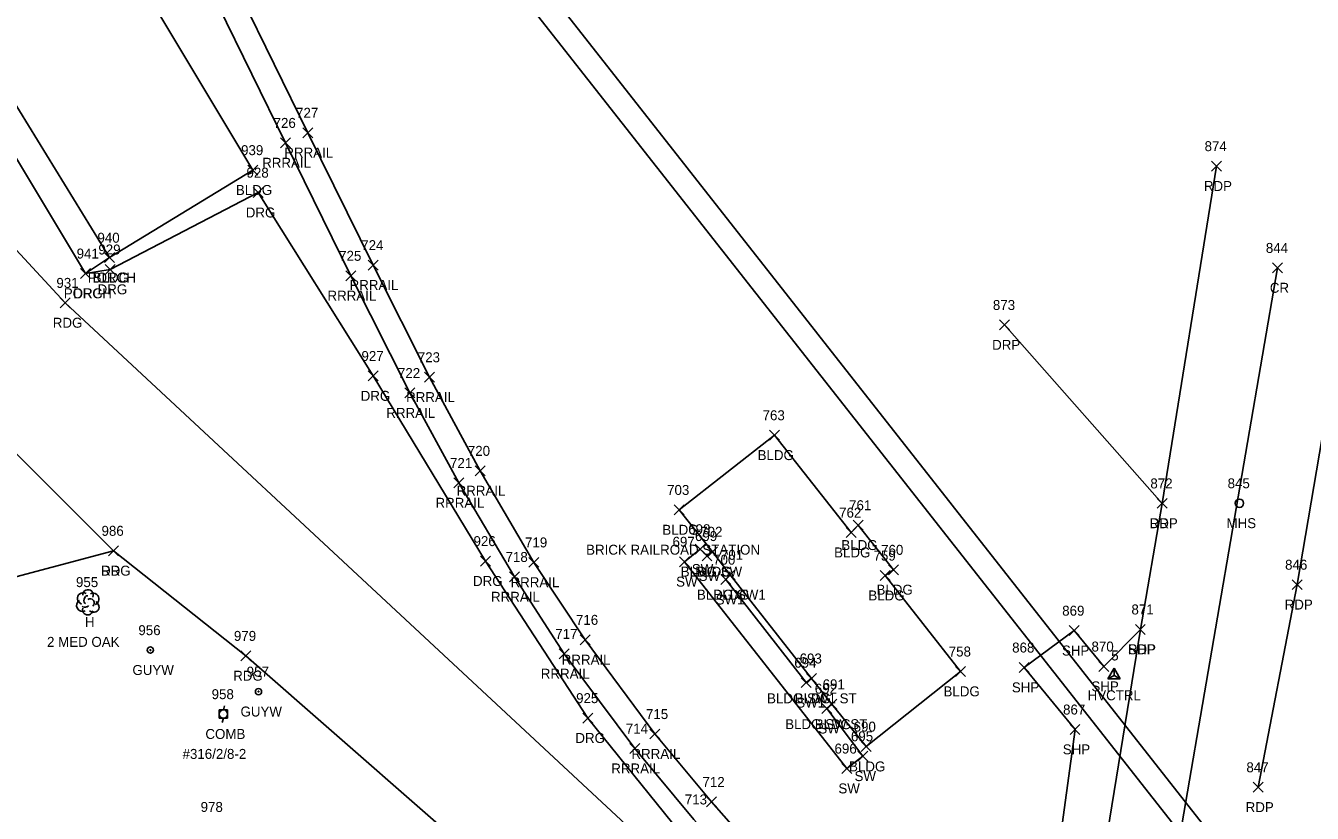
# Model space of a CAD drawing. Extents: x 1615599 to 1619911, y 273782 to 280437.
# Drawn here: x 1616311.5 to 1616569.8, y 279843.1 to 280001.3 of the extents above; entities that cross this region are included whole.
import ezdxf

# ---------------------------------------------------------------- set-up
doc = ezdxf.new("R2010")
doc.units = 0
for name, color, linetype in [('C_A', 7, 'Continuous'), ('C_I', 7, 'Continuous'), ('CPSM', 7, 'Continuous'), ('L_A', 7, 'Continuous'), ('L_C', 7, 'Continuous'), ('L_I', 7, 'Continuous'), ('L_TIC', 7, 'Continuous'), ('LBC', 7, 'Continuous'), ('LBF', 7, 'Continuous'), ('LTD', 7, 'Continuous'), ('P_A', 7, 'Continuous'), ('P_I', 7, 'Continuous'), ('P_TIC', 7, 'Continuous'), ('PET', 7, 'Continuous'), ('PEU', 7, 'Continuous'), ('PRC', 7, 'Continuous'), ('PSP', 7, 'Continuous'), ('R_A', 7, 'Continuous'), ('R_I', 7, 'Continuous'), ('R_TIC', 7, 'Continuous'), ('RDG', 7, 'Continuous'), ('RDP', 7, 'Continuous'), ('RR', 7, 'Continuous'), ('RSW', 7, 'Continuous'), ('U_A', 7, 'Continuous'), ('U_C', 7, 'Continuous'), ('U_I', 7, 'Continuous'), ('UP', 7, 'Continuous'), ('UPGW', 7, 'Continuous'), ('USMH', 7, 'Continuous')]:
    doc.layers.add(name, color=color, linetype=linetype)

msp = doc.modelspace()

# ---------------------------------------------------------------- linework, layer by layer
at = {"layer": 'CPSM'}
for p, q in [((1616528.77, 279870.08), (1616530.02, 279872.24)), ((1616531.27, 279870.08), (1616530.02, 279872.24)), ((1616530.03, 279870.8), (1616530.02, 279872.24)), ((1616528.77, 279870.08), (1616530.03, 279870.8)), ((1616528.77, 279870.08), (1616531.27, 279870.08)), ((1616530.03, 279870.8), (1616530.03, 279870.8)), ((1616530.03, 279870.8), (1616531.27, 279870.08))]:
    msp.add_line(p, q, dxfattribs=at)
at = {"layer": 'L_TIC'}
for points in [[(1616356.12, 279971.28), (1616358.12, 279973.28)], [(1616358.12, 279971.28), (1616356.12, 279973.28)], [(1616327.36, 279953.69), (1616329.36, 279955.69)], [(1616329.36, 279953.69), (1616327.36, 279955.69)], [(1616327.36, 279953.69), (1616329.36, 279955.69)], [(1616329.36, 279953.69), (1616327.36, 279955.69)], [(1616322.53, 279950.52), (1616324.53, 279952.52)], [(1616324.53, 279950.52), (1616322.53, 279952.52)], [(1616460.87, 279918.04), (1616462.87, 279920.04)], [(1616462.87, 279918.04), (1616460.87, 279920.04)], [(1616460.87, 279918.04), (1616462.87, 279920.04)], [(1616462.87, 279918.04), (1616460.87, 279920.04)], [(1616441.73, 279903.04), (1616443.73, 279905.04)], [(1616443.73, 279903.04), (1616441.73, 279905.04)], [(1616476.24, 279898.49), (1616478.24, 279900.49)], [(1616478.24, 279898.49), (1616476.24, 279900.49)], [(1616477.68, 279899.97), (1616479.68, 279901.97)], [(1616479.68, 279899.97), (1616477.68, 279901.97)], [(1616448.38, 279894.64), (1616450.38, 279896.64)], [(1616450.38, 279894.64), (1616448.38, 279896.64)], [(1616451.97, 279890.01), (1616453.97, 279892.01)], [(1616453.97, 279890.01), (1616451.97, 279892.01)], [(1616483.1, 279889.85), (1616485.1, 279891.85)], [(1616485.1, 279889.85), (1616483.1, 279891.85)], [(1616484.75, 279891.01), (1616486.75, 279893.01)], [(1616486.75, 279891.01), (1616484.75, 279893.01)], [(1616468.31, 279869.19), (1616470.31, 279871.19)], [(1616470.31, 279869.19), (1616468.31, 279871.19)], [(1616498.2, 279870.59), (1616500.2, 279872.59)], [(1616500.2, 279870.59), (1616498.2, 279872.59)], [(1616472.36, 279864), (1616474.36, 279866)], [(1616474.36, 279864), (1616472.36, 279866)], [(1616479.23, 279855.51), (1616481.23, 279857.51)], [(1616481.23, 279855.51), (1616479.23, 279857.51)], [(1616479.23, 279855.51), (1616481.23, 279857.51)], [(1616481.23, 279855.51), (1616479.23, 279857.51)]]:
    msp.add_lwpolyline(points, dxfattribs=at)
at = {"layer": 'LBC'}
for points in [[(1616260.86, 280142.43), (1616270.81, 280125.23), (1616271.71, 280125.76), (1616321.31, 280044.41), (1616318.76, 280042.81), (1616339.97, 280008.45), (1616336.65, 280006.38), (1616357.12, 279972.28), (1616328.36, 279954.69), (1616257.78, 280069.65), (1616226.23, 280122.19)], [(1616480.23, 279856.51), (1616473.36, 279865), (1616469.31, 279870.19), (1616452.97, 279891.01), (1616449.38, 279895.64), (1616442.73, 279904.04), (1616461.87, 279919.04)], [(1616480.23, 279856.51), (1616499.2, 279871.59), (1616484.1, 279890.85), (1616485.75, 279892.01), (1616478.68, 279900.97), (1616477.24, 279899.49), (1616461.87, 279919.04)]]:
    msp.add_lwpolyline(points, dxfattribs=at)
at = {"layer": 'LBF'}
msp.add_lwpolyline([(1616328.36, 279954.69), (1616323.53, 279951.52), (1616279.95, 280024.05), (1616274.42, 280020.51), (1616248.28, 280063.02), (1616257.78, 280069.65)], dxfattribs=at)
at = {"layer": 'LTD'}
msp.add_line((1616323.96, 279885.53), (1616323.96, 279885.53), dxfattribs=at)
msp.add_line((1616323.96, 279885.53), (1616323.96, 279885.53), dxfattribs=at)
msp.add_arc((1616324.01, 279886.96), 1.05, 335.5272, 180.9563, dxfattribs=at)
for centre, major_axis, ratio, start_param, end_param in [((1616323.17, 279886.19), (1.21, -0.51), 0.895232, 1.570796, 4.712389), ((1616323.75, 279885.98), (-0.208, -0.792), 0.645439, 3.141593, 6.283185), ((1616325, 279886.11), (-1.14, -0.48), 0.949671, 1.570796, 4.712389), ((1616322.88, 279884.82), (0.58, -1.04), 0.959034, 3.141593, 6.283185), ((1616323.96, 279884.03), (0.26, 1.06), 0.942809, 1.570796, 4.712389), ((1616323.5, 279884.78), (-0.625, -0.083), 0.423636, 0, 3.141593), ((1616324.46, 279885.36), (-0.5, 0.667), 0.989748, 3.141593, 6.283185), ((1616324.96, 279884.69), (-1.09, 0.79), 0.841452, 1.570796, 4.712389)]:
    msp.add_ellipse(centre, major_axis=major_axis, ratio=ratio, start_param=start_param, end_param=end_param, dxfattribs=at)
at = {"layer": 'P_TIC'}
for points in [[(1616549.57, 279972.08), (1616551.57, 279974.08)], [(1616551.57, 279972.08), (1616549.57, 279974.08)], [(1616561.87, 279951.64), (1616563.87, 279953.64)], [(1616563.87, 279951.64), (1616561.87, 279953.64)], [(1616318.46, 279944.62), (1616320.46, 279946.62)], [(1616320.46, 279944.62), (1616318.46, 279946.62)], [(1616538.68, 279904.35), (1616540.68, 279906.35)], [(1616540.68, 279904.35), (1616538.68, 279906.35)], [(1616328.14, 279894.83), (1616330.14, 279896.83)], [(1616330.14, 279894.83), (1616328.14, 279896.83)], [(1616565.79, 279888.02), (1616567.79, 279890.02)], [(1616567.79, 279888.02), (1616565.79, 279890.02)], [(1616521.04, 279878.79), (1616523.04, 279880.79)], [(1616523.04, 279878.79), (1616521.04, 279880.79)], [(1616534.31, 279879.04), (1616536.31, 279881.04)], [(1616536.31, 279879.04), (1616534.31, 279881.04)], [(1616534.31, 279879.04), (1616536.31, 279881.04)], [(1616536.31, 279879.04), (1616534.31, 279881.04)], [(1616354.68, 279873.73), (1616356.68, 279875.73)], [(1616356.68, 279873.73), (1616354.68, 279875.73)], [(1616510.98, 279871.39), (1616512.98, 279873.39)], [(1616512.98, 279871.39), (1616510.98, 279873.39)], [(1616526.95, 279871.59), (1616528.95, 279873.59)], [(1616528.95, 279871.59), (1616526.95, 279873.59)], [(1616521.19, 279858.94), (1616523.19, 279860.94)], [(1616523.19, 279858.94), (1616521.19, 279860.94)], [(1616557.96, 279847.34), (1616559.96, 279849.34)], [(1616559.96, 279847.34), (1616557.96, 279849.34)]]:
    msp.add_lwpolyline(points, dxfattribs=at)
at = {"layer": 'PET'}
for points in [[(1616501.73, 279478.79), (1616504.15, 279516.53), (1616502.36, 279521.09), (1616509.74, 279623.18), (1616513.26, 279680.58), (1616517.86, 279738.11), (1616521.66, 279796.02), (1616535.31, 279880.04), (1616539.68, 279905.35), (1616550.57, 279973.08)], [(1616577.39, 279951.25), (1616566.79, 279889.02), (1616558.96, 279848.34)]]:
    msp.add_lwpolyline(points, dxfattribs=at)
at = {"layer": 'PEU'}
for points in [[(1616499.74, 279780.98), (1616479.11, 279797), (1616319.46, 279945.62), (1616274.32, 279994.35), (1616255.18, 280018.22), (1616235.11, 280063.13), (1616219.63, 280113.45), (1616199.45, 280157.82), (1616176.87, 280194.27), (1616140.8, 280248.09)], [(1616486.88, 279757.56), (1616476.4, 279764.58), (1616449.89, 279788.09), (1616430.61, 279808), (1616410.01, 279827.22), (1616355.68, 279874.73), (1616329.14, 279895.83), (1616251.77, 279973.13), (1616240.04, 279993.6), (1616211.88, 280076.79), (1616204.14, 280097.8), (1616191.71, 280134.04), (1616179.76, 280157.24), (1616153.69, 280197.29), (1616148.4, 280204.31)]]:
    msp.add_lwpolyline(points, dxfattribs=at)
at = {"layer": 'PRC'}
msp.add_lwpolyline([(1616513.97, 279478.68), (1616523.34, 279622.43), (1616526.18, 279679.14), (1616531, 279739.46), (1616538.76, 279812.35), (1616562.87, 279952.64)], dxfattribs=at)
at = {"layer": 'PSP'}
msp.add_lwpolyline([(1616512.64, 279790.01), (1616522.19, 279859.94), (1616511.98, 279872.39), (1616522.04, 279879.79), (1616527.95, 279872.59), (1616535.31, 279880.04)], dxfattribs=at)
at = {"layer": 'R_TIC'}
for points in [[(1616367.15, 279978.78), (1616369.15, 279980.78)], [(1616369.15, 279978.78), (1616367.15, 279980.78)], [(1616362.7, 279976.75), (1616364.7, 279978.75)], [(1616364.7, 279976.75), (1616362.7, 279978.75)], [(1616357.21, 279966.76), (1616359.21, 279968.76)], [(1616359.21, 279966.76), (1616357.21, 279968.76)], [(1616380.25, 279952.2), (1616382.25, 279954.2)], [(1616382.25, 279952.2), (1616380.25, 279954.2)], [(1616322.53, 279950.52), (1616324.53, 279952.52)], [(1616324.53, 279950.52), (1616322.53, 279952.52)], [(1616327.46, 279951.33), (1616329.46, 279953.33)], [(1616329.46, 279951.33), (1616327.46, 279953.33)], [(1616375.81, 279950.06), (1616377.81, 279952.06)], [(1616377.81, 279950.06), (1616375.81, 279952.06)], [(1616507.06, 279940.18), (1616509.06, 279942.18)], [(1616509.06, 279940.18), (1616507.06, 279942.18)], [(1616380.28, 279929.94), (1616382.28, 279931.94)], [(1616382.28, 279929.94), (1616380.28, 279931.94)], [(1616391.59, 279929.69), (1616393.59, 279931.69)], [(1616393.59, 279929.69), (1616391.59, 279931.69)], [(1616387.61, 279926.52), (1616389.61, 279928.52)], [(1616389.61, 279926.52), (1616387.61, 279928.52)], [(1616401.73, 279910.89), (1616403.73, 279912.89)], [(1616403.73, 279910.89), (1616401.73, 279912.89)], [(1616397.5, 279908.46), (1616399.5, 279910.46)], [(1616399.5, 279908.46), (1616397.5, 279910.46)], [(1616538.68, 279904.35), (1616540.68, 279906.35)], [(1616540.68, 279904.35), (1616538.68, 279906.35)], [(1616445.94, 279895.15), (1616447.94, 279897.15)], [(1616447.94, 279895.15), (1616445.94, 279897.15)], [(1616328.14, 279894.83), (1616330.14, 279896.83)], [(1616330.14, 279894.83), (1616328.14, 279896.83)], [(1616402.84, 279892.76), (1616404.84, 279894.76)], [(1616404.84, 279892.76), (1616402.84, 279894.76)], [(1616412.56, 279892.5), (1616414.56, 279894.5)], [(1616414.56, 279892.5), (1616412.56, 279894.5)], [(1616442.79, 279892.63), (1616444.79, 279894.63)], [(1616444.79, 279892.63), (1616442.79, 279894.63)], [(1616447.3, 279893.78), (1616449.3, 279895.78)], [(1616449.3, 279893.78), (1616447.3, 279895.78)], [(1616448.38, 279894.64), (1616450.38, 279896.64)], [(1616450.38, 279894.64), (1616448.38, 279896.64)], [(1616451.97, 279890.01), (1616453.97, 279892.01)], [(1616453.97, 279890.01), (1616451.97, 279892.01)], [(1616408.64, 279889.58), (1616410.64, 279891.58)], [(1616410.64, 279889.58), (1616408.64, 279891.58)], [(1616451.06, 279889.04), (1616453.06, 279891.04)], [(1616453.06, 279889.04), (1616451.06, 279891.04)], [(1616422.84, 279876.95), (1616424.84, 279878.95)], [(1616424.84, 279876.95), (1616422.84, 279878.95)], [(1616418.63, 279874.14), (1616420.63, 279876.14)], [(1616420.63, 279874.14), (1616418.63, 279876.14)], [(1616468.31, 279869.19), (1616470.31, 279871.19)], [(1616470.31, 279869.19), (1616468.31, 279871.19)], [(1616467.24, 279868.34), (1616469.24, 279870.34)], [(1616469.24, 279868.34), (1616467.24, 279870.34)], [(1616472.36, 279864), (1616474.36, 279866)], [(1616474.36, 279864), (1616472.36, 279866)], [(1616471.35, 279863.13), (1616473.35, 279865.13)], [(1616473.35, 279863.13), (1616471.35, 279865.13)], [(1616423.38, 279861.23), (1616425.38, 279863.23)], [(1616425.38, 279861.23), (1616423.38, 279863.23)], [(1616436.84, 279858.03), (1616438.84, 279860.03)], [(1616438.84, 279858.03), (1616436.84, 279860.03)], [(1616432.79, 279855.11), (1616434.79, 279857.11)], [(1616434.79, 279855.11), (1616432.79, 279857.11)], [(1616478.61, 279853.57), (1616480.61, 279855.57)], [(1616480.61, 279853.57), (1616478.61, 279855.57)], [(1616475.37, 279851.1), (1616477.37, 279853.1)], [(1616477.37, 279851.1), (1616475.37, 279853.1)], [(1616448.19, 279844.4), (1616450.19, 279846.4)], [(1616450.19, 279844.4), (1616448.19, 279846.4)]]:
    msp.add_lwpolyline(points, dxfattribs=at)
at = {"layer": 'RDG'}
for points in [[(1616479.11, 279797), (1616452.08, 279827.9), (1616424.38, 279862.23), (1616403.84, 279893.76), (1616381.28, 279930.94), (1616358.21, 279967.76), (1616328.46, 279952.33), (1616323.53, 279951.52)], [(1616329.14, 279895.83), (1616292.13, 279885.95), (1616252.07, 279884.53), (1616218.26, 279864.37), (1616210.2, 279851.21)]]:
    msp.add_lwpolyline(points, dxfattribs=at)
at = {"layer": 'RDP'}
msp.add_lwpolyline([(1616539.68, 279905.35), (1616508.06, 279941.18)], dxfattribs=at)
at = {"layer": 'RR'}
for points in [[(1618863.67, 276894.43), (1618803.13, 276971.25), (1618287.89, 277627.49), (1618272.16, 277647.46), (1617630.42, 278463.6), (1617620.37, 278476.22), (1617582.75, 278523.92), (1617266.97, 278926.89), (1616715.35, 279628.09), (1616637.52, 279726.94), (1616590.36, 279786.85), (1616151.06, 280346.19)], [(1618859.75, 276891.53), (1618799.24, 276968.15), (1618284.94, 277623.12), (1618268.81, 277643.64), (1617626.81, 278460.24), (1617616.13, 278473.64), (1617546.95, 278561.72), (1617499.49, 278621.79), (1617406.55, 278740.52), (1617357.63, 278802.9), (1617271.97, 278912.55), (1616838.51, 279463.88), (1616791.25, 279524.04), (1616711.4, 279625.23), (1616195.43, 280281.84), (1616147.06, 280342.91)], [(1616578.78, 279727.56), (1616559.36, 279743.25), (1616547.84, 279752.47), (1616532.45, 279765.05), (1616519.03, 279776.56), (1616509.64, 279784.79), (1616496.17, 279796.99), (1616483.02, 279809.54), (1616469.51, 279823.1), (1616459.09, 279834.19), (1616449.19, 279845.4), (1616437.84, 279859.03), (1616423.84, 279877.95), (1616413.56, 279893.5), (1616402.73, 279911.89), (1616392.59, 279930.69), (1616381.25, 279953.2), (1616368.15, 279979.78), (1616347.86, 280021.18)], [(1616575.93, 279723.48), (1616556.08, 279739.45), (1616545.23, 279748.16), (1616531.41, 279759.44), (1616516, 279772.44), (1616507.27, 279780.31), (1616493.17, 279793.09), (1616479.92, 279805.59), (1616465.51, 279820.07), (1616455.17, 279831.23), (1616445.64, 279841.88), (1616433.79, 279856.11), (1616419.63, 279875.14), (1616409.64, 279890.58), (1616398.5, 279909.46), (1616388.61, 279927.52), (1616376.81, 279951.06), (1616363.7, 279977.75), (1616343.37, 280019.21)]]:
    msp.add_lwpolyline(points, dxfattribs=at)
at = {"layer": 'RSW'}
for points in [[(1616473.36, 279865), (1616472.35, 279864.13), (1616479.61, 279854.57), (1616476.37, 279852.1), (1616443.79, 279893.63), (1616446.94, 279896.15), (1616448.3, 279894.78), (1616449.38, 279895.64)], [(1616469.31, 279870.19), (1616468.24, 279869.34), (1616452.06, 279890.04), (1616452.97, 279891.01)]]:
    msp.add_lwpolyline(points, dxfattribs=at)
at = {"layer": 'UP'}
for p, q in [((1616350.37, 279862.2), (1616350.37, 279863.86)), ((1616350.37, 279863.86), (1616352.03, 279863.86)), ((1616351.45, 279864.7), (1616351.2, 279863.86)), ((1616352.03, 279863.86), (1616352.03, 279862.2)), ((1616352.03, 279862.2), (1616350.37, 279862.2)), ((1616350.95, 279861.36), (1616351.2, 279862.2)), ((1616351.2, 279863.03), (1616351.2, 279863.03))]:
    msp.add_line(p, q, dxfattribs=at)
msp.add_circle((1616351.2, 279863.03), 0.833, dxfattribs=at)
at = {"layer": 'UPGW'}
for centre, radius in [((1616336.55, 279875.88), 0.625), ((1616336.55, 279875.88), 0.0833), ((1616358.25, 279867.54), 0.625), ((1616358.25, 279867.54), 0.0833)]:
    msp.add_circle(centre, radius, dxfattribs=at)
at = {"layer": 'USMH'}
for p, q in [((1616555.2, 279905.37), (1616555.2, 279905.37)), ((1616556.03, 279905.37), (1616556.03, 279905.37))]:
    msp.add_line(p, q, dxfattribs=at)
msp.add_circle((1616555.2, 279905.37), 0.833, dxfattribs=at)

# ---------------------------------------------------------------- texts
at = {"layer": 'C_A'}
msp.add_text('HVCTRL', height=2, dxfattribs=at).set_placement((1616524.72, 279865.8))
at = {"layer": 'C_I'}
msp.add_text('5', height=2, dxfattribs=at).set_placement((1616529.46, 279873.8))
at = {"layer": 'L_A'}
for s, p in [('BLDG', (1616353.71, 279967.28)), ('PORCH', (1616323.98, 279949.69)), ('BLDG', (1616324.95, 279949.69)), ('PORCH', (1616319.16, 279946.52)), ('BLDG', (1616458.46, 279914.04)), ('BLDG', (1616458.46, 279914.04)), ('BLDG', (1616439.33, 279899.04)), ('BLDG', (1616475.27, 279895.97)), ('BLDG', (1616473.83, 279894.49)), ('BLDG', (1616445.97, 279890.64)), ('BLDG', (1616449.56, 279886.01)), ('BLDG', (1616480.7, 279885.85)), ('BLDG', (1616482.34, 279887.01)), ('H', (1616323.39, 279880.53)), ('BLDG', (1616495.79, 279866.59)), ('BLDG', (1616465.9, 279865.19)), ('BLDG', (1616469.95, 279860)), ('BLDG', (1616476.82, 279851.51)), ('BLDG', (1616476.82, 279851.51))]:
    msp.add_text(s, height=2, dxfattribs=at).set_placement(p)
at = {"layer": 'L_C'}
for s, p in [('BRICK RAILROAD STATION', (1616424.03, 279895.04)), ('2 MED OAK', (1616315.79, 279876.53))]:
    msp.add_text(s, height=2, dxfattribs=at).set_placement(p)
at = {"layer": 'L_I'}
for s, p in [('939', (1616354.75, 279975.28)), ('940', (1616325.91, 279957.69)), ('940', (1616325.91, 279957.69)), ('941', (1616321.74, 279954.52)), ('763', (1616459.46, 279922.04)), ('763', (1616459.46, 279922.04)), ('703', (1616440.29, 279907.04)), ('761', (1616476.83, 279903.97)), ('762', (1616474.83, 279902.49)), ('702', (1616446.94, 279898.64)), ('760', (1616483.26, 279895.01)), ('701', (1616451.09, 279894.01)), ('759', (1616481.73, 279893.85)), ('955', (1616321.6, 279888.53)), ('758', (1616496.84, 279874.59)), ('693', (1616466.9, 279873.19)), ('691', (1616471.52, 279868)), ('690', (1616477.74, 279859.51)), ('690', (1616477.74, 279859.51))]:
    msp.add_text(s, height=2, dxfattribs=at).set_placement(p)
at = {"layer": 'P_A'}
for s, p in [('RDP', (1616548.06, 279968.08)), ('CR', (1616561.31, 279947.64)), ('RDG', (1616316.95, 279940.62)), ('RDP', (1616537.17, 279900.35)), ('RDG', (1616326.63, 279890.83)), ('RDP', (1616564.28, 279884.02)), ('SHP', (1616519.57, 279874.79)), ('SHP', (1616532.85, 279875.04)), ('RDP', (1616532.8, 279875.04)), ('RDG', (1616353.17, 279869.73)), ('SHP', (1616509.51, 279867.39)), ('SHP', (1616525.48, 279867.59)), ('SHP', (1616519.73, 279854.94)), ('RDP', (1616556.45, 279843.34))]:
    msp.add_text(s, height=2, dxfattribs=at).set_placement(p)
at = {"layer": 'P_I'}
for s, p in [('874', (1616548.21, 279976.08)), ('844', (1616560.51, 279955.64)), ('931', (1616317.67, 279948.62)), ('872', (1616537.32, 279908.35)), ('986', (1616326.73, 279898.83)), ('846', (1616564.37, 279892.02)), ('869', (1616519.62, 279882.79)), ('871', (1616533.52, 279883.04)), ('871', (1616533.52, 279883.04)), ('979', (1616353.31, 279877.73)), ('868', (1616509.57, 279875.39)), ('870', (1616525.5, 279875.59)), ('867', (1616519.79, 279862.94)), ('847', (1616556.6, 279851.34))]:
    msp.add_text(s, height=2, dxfattribs=at).set_placement(p)
at = {"layer": 'R_A'}
for s, p in [('RRRAIL', (1616358.99, 279972.75)), ('RRRAIL', (1616363.44, 279974.78)), ('DRG', (1616355.69, 279962.76)), ('DRG', (1616321.02, 279946.52)), ('DRG', (1616325.94, 279947.33)), ('RRRAIL', (1616376.54, 279948.2)), ('RRRAIL', (1616372.1, 279946.06)), ('DRP', (1616505.55, 279936.18)), ('DRG', (1616378.77, 279925.94)), ('RRRAIL', (1616387.88, 279925.69)), ('RRRAIL', (1616383.91, 279922.52)), ('RRRAIL', (1616398.02, 279906.89)), ('RRRAIL', (1616393.79, 279904.46)), ('DRP', (1616537.17, 279900.35)), ('DRG', (1616326.63, 279890.83)), ('BLDG SW', (1616443.02, 279890.64)), ('SW', (1616445.25, 279891.15)), ('SW', (1616446.62, 279889.78)), ('DRG', (1616401.32, 279888.76)), ('RRRAIL', (1616408.85, 279888.5)), ('SW', (1616442.1, 279888.63)), ('RRRAIL', (1616404.93, 279885.58)), ('BLDG SW1', (1616446.28, 279886.01)), ('SW1', (1616450.04, 279885.04)), ('RRRAIL', (1616419.13, 279872.95)), ('RRRAIL', (1616414.93, 279870.14)), ('BLDG SW1 ST', (1616460.36, 279865.19)), ('SW1', (1616466.23, 279864.34)), ('BLDG SW ST', (1616464, 279860)), ('SW', (1616470.66, 279859.13)), ('DRG', (1616421.87, 279857.23)), ('RRRAIL', (1616433.13, 279854.03)), ('RRRAIL', (1616429.08, 279851.11)), ('SW', (1616477.92, 279849.57)), ('SW', (1616474.68, 279847.1))]:
    msp.add_text(s, height=2, dxfattribs=at).set_placement(p)
at = {"layer": 'R_I'}
for s, p in [('727', (1616365.79, 279982.78)), ('726', (1616361.28, 279980.75)), ('928', (1616355.84, 279970.76)), ('941', (1616321.74, 279954.52)), ('929', (1616326.09, 279955.33)), ('724', (1616378.88, 279956.2)), ('725', (1616374.44, 279954.06)), ('873', (1616505.7, 279944.18)), ('927', (1616378.92, 279933.94)), ('723', (1616390.23, 279933.69)), ('722', (1616386.25, 279930.52)), ('720', (1616400.28, 279914.89)), ('721', (1616396.7, 279912.46)), ('872', (1616537.32, 279908.35)), ('986', (1616326.73, 279898.83)), ('698', (1616444.53, 279899.15)), ('699', (1616445.89, 279897.78)), ('702', (1616446.94, 279898.64)), ('926', (1616401.42, 279896.76)), ('719', (1616411.76, 279896.5)), ('697', (1616441.38, 279896.63)), ('718', (1616407.85, 279893.58)), ('700', (1616449.53, 279893.04)), ('701', (1616451.09, 279894.01)), ('716', (1616421.99, 279880.95)), ('717', (1616417.84, 279878.14)), ('694', (1616465.83, 279872.34)), ('693', (1616466.9, 279873.19)), ('692', (1616469.94, 279867.13)), ('691', (1616471.52, 279868)), ('925', (1616422.02, 279865.23)), ('715', (1616436.05, 279862.03)), ('714', (1616431.99, 279859.11)), ('695', (1616477.2, 279857.57)), ('696', (1616473.9, 279855.1)), ('712', (1616447.39, 279848.4)), ('978', (1616346.63, 279843.38)), ('713', (1616443.84, 279844.88))]:
    msp.add_text(s, height=2, dxfattribs=at).set_placement(p)
at = {"layer": 'U_A'}
for s, p in [('MHS', (1616552.61, 279900.37)), ('GUYW', (1616332.94, 279870.88)), ('GUYW', (1616354.64, 279862.54)), ('COMB', (1616347.59, 279858.03))]:
    msp.add_text(s, height=2, dxfattribs=at).set_placement(p)
at = {"layer": 'U_C'}
msp.add_text('#316/2/8-2', height=2, dxfattribs=at).set_placement((1616343, 279854.03))
at = {"layer": 'U_I'}
for s, p in [('845', (1616552.83, 279908.37)), ('956', (1616334.13, 279878.88)), ('957', (1616355.88, 279870.54)), ('958', (1616348.84, 279866.03))]:
    msp.add_text(s, height=2, dxfattribs=at).set_placement(p)

doc.saveas('drawing.dxf')
